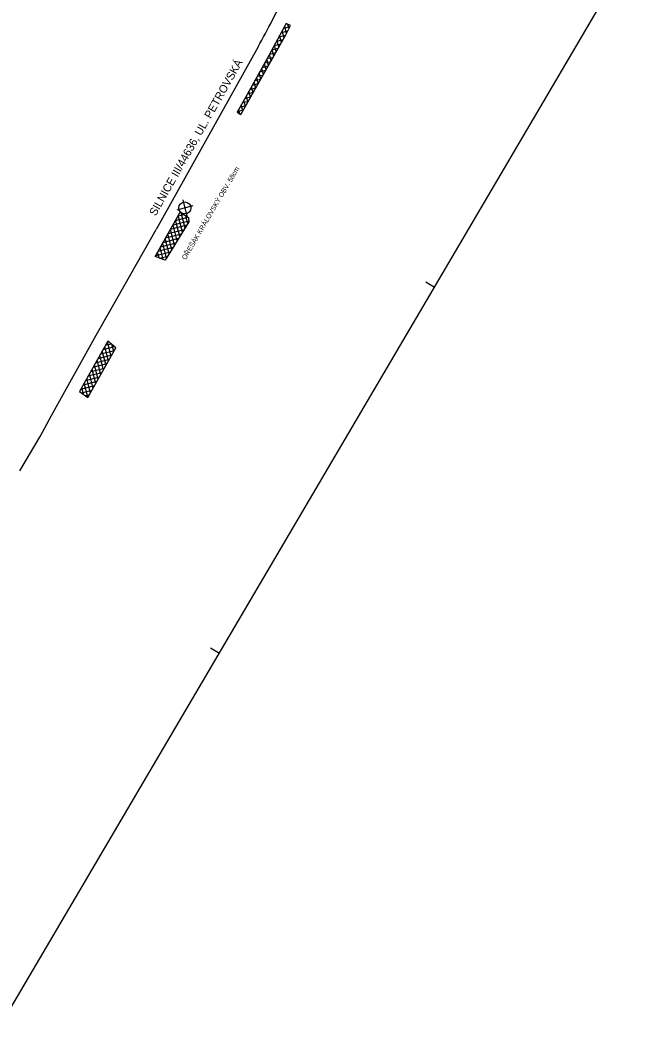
# Model space of a CAD drawing. Extents: x -559605 to -559051, y -1075984 to -1075185.
# Drawn here: x -559472.7 to -559320, y -1075984.5 to -1075737.3 of the extents above; entities that cross this region are included whole.
import ezdxf

# ---------------------------------------------------------------- set-up
doc = ezdxf.new("R2010")
doc.units = 0
for name, color, linetype in [('_kaceni_stromu', 7, 'Continuous'), ('_odstraneni_krovin', 7, 'Continuous'), ('_zarezani_asfaltu', 7, 'Continuous'), ('Legenda', 7, 'Continuous'), ('popis', 7, 'Continuous'), ('Ramecek_rozpiska', 7, 'Continuous')]:
    doc.layers.add(name, color=color, linetype=linetype)

msp = doc.modelspace()

# ---------------------------------------------------------------- linework, layer by layer
at = {"layer": '_kaceni_stromu'}
for p, q in [((-559429.87, -1075783.31), (-559433.87, -1075784.35)), ((-559432.39, -1075781.83), (-559431.35, -1075785.83))]:
    msp.add_line(p, q, dxfattribs=at)
msp.add_circle((-559431.87, -1075783.83), 1.49, dxfattribs=at)
at = {"layer": '_odstraneni_krovin'}
for p, q in [((-559407.41, -1075739.32), (-559405.83, -1075738.91)), ((-559406.7, -1075740.65), (-559407.17, -1075738.87)), ((-559406.83, -1075738.24), (-559406.83, -1075738.24)), ((-559406.09, -1075739.43), (-559406.35, -1075738.43)), ((-559409.15, -1075742.56), (-559407.53, -1075742.14)), ((-559408.57, -1075741.48), (-559406.91, -1075741.05)), ((-559407.97, -1075742.93), (-559408.42, -1075741.2)), ((-559407.99, -1075740.4), (-559406.37, -1075739.98)), ((-559407.33, -1075741.8), (-559407.79, -1075740.03)), ((-559410.31, -1075744.73), (-559408.76, -1075744.32)), ((-559409.88, -1075746.31), (-559410.3, -1075744.7)), ((-559409.73, -1075743.65), (-559408.14, -1075743.23)), ((-559409.24, -1075745.18), (-559409.67, -1075743.54)), ((-559408.61, -1075744.06), (-559409.05, -1075742.37)), ((-559411.16, -1075748.57), (-559411.55, -1075747.04)), ((-559411.47, -1075746.89), (-559409.99, -1075746.5)), ((-559410.52, -1075747.44), (-559410.93, -1075745.87)), ((-559410.89, -1075745.81), (-559409.37, -1075745.41)), ((-559412.43, -1075750.82), (-559412.82, -1075749.3)), ((-559412.69, -1075749.06), (-559411.22, -1075748.68)), ((-559411.79, -1075749.69), (-559412.19, -1075748.17)), ((-559412.08, -1075747.97), (-559410.61, -1075747.59)), ((-559414.52, -1075752.33), (-559413.07, -1075751.95)), ((-559413.7, -1075753.08), (-559414.09, -1075751.57)), ((-559413.91, -1075751.24), (-559412.45, -1075750.86)), ((-559413.07, -1075751.95), (-559413.46, -1075750.44)), ((-559413.3, -1075750.15), (-559411.84, -1075749.77)), ((-559415.74, -1075754.5), (-559414.3, -1075754.13)), ((-559414.98, -1075755.33), (-559415.37, -1075753.84)), ((-559415.13, -1075753.42), (-559413.68, -1075753.04)), ((-559414.34, -1075754.2), (-559414.73, -1075752.7)), ((-559416.96, -1075756.68), (-559415.53, -1075756.31)), ((-559416.25, -1075757.59), (-559416.64, -1075756.1)), ((-559416.35, -1075755.59), (-559414.91, -1075755.22)), ((-559415.62, -1075756.46), (-559416, -1075754.97)), ((-559418.28, -1075760.52), (-559418.56, -1075759.46)), ((-559418.21, -1075758.87), (-559416.76, -1075758.49)), ((-559417.53, -1075759.84), (-559417.92, -1075758.34)), ((-559417.59, -1075757.77), (-559416.15, -1075757.4)), ((-559416.89, -1075758.71), (-559417.28, -1075757.23)), ((-559418.84, -1075759.96), (-559417.38, -1075759.58)), ((-559418.02, -1075760.67), (-559417.99, -1075760.67)), ((-559434.17, -1075786.9), (-559431.1, -1075786.1)), ((-559433.56, -1075785.81), (-559432.12, -1075785.44)), ((-559432.45, -1075789.85), (-559433.52, -1075785.73)), ((-559431.79, -1075788.79), (-559432.77, -1075785.01)), ((-559431.14, -1075787.73), (-559431.65, -1075785.74)), ((-559436.01, -1075790.16), (-559432, -1075789.12)), ((-559434.41, -1075793.03), (-559435.42, -1075789.13)), ((-559435.39, -1075789.08), (-559431.31, -1075788.02)), ((-559433.76, -1075791.97), (-559434.79, -1075788)), ((-559434.78, -1075787.99), (-559430.89, -1075786.98)), ((-559433.1, -1075790.91), (-559434.15, -1075786.87)), ((-559437.23, -1075792.34), (-559433.36, -1075791.34)), ((-559435.72, -1075795.15), (-559436.7, -1075791.39)), ((-559436.62, -1075791.25), (-559432.68, -1075790.23)), ((-559435.06, -1075794.09), (-559436.06, -1075790.26)), ((-559438.45, -1075794.52), (-559434.73, -1075793.55)), ((-559437.21, -1075796.59), (-559437.97, -1075793.65)), ((-559437.84, -1075793.43), (-559434.05, -1075792.45)), ((-559436.37, -1075796.21), (-559437.33, -1075792.52)), ((-559439.07, -1075795.61), (-559435.41, -1075794.66)), ((-559438.24, -1075796.19), (-559438.6, -1075794.79)), ((-559438.05, -1075796.27), (-559436.1, -1075795.77)), ((-559452.08, -1075818.86), (-559449.25, -1075818.13)), ((-559450.74, -1075821.62), (-559451.65, -1075818.09)), ((-559451.47, -1075817.78), (-559450.1, -1075817.42)), ((-559450.1, -1075820.49), (-559451.02, -1075816.96)), ((-559449.46, -1075819.36), (-559449.93, -1075817.56)), ((-559453.92, -1075822.13), (-559450.53, -1075821.25)), ((-559453.3, -1075821.04), (-559449.92, -1075820.16)), ((-559452.01, -1075823.88), (-559452.92, -1075820.36)), ((-559452.69, -1075819.95), (-559449.3, -1075819.07)), ((-559451.37, -1075822.75), (-559452.29, -1075819.23)), ((-559455.14, -1075824.31), (-559451.75, -1075823.43)), ((-559453.92, -1075827.27), (-559454.83, -1075823.76)), ((-559454.53, -1075823.22), (-559451.14, -1075822.34)), ((-559453.28, -1075826.14), (-559454.19, -1075822.63)), ((-559452.64, -1075825.01), (-559453.56, -1075821.49)), ((-559456.36, -1075826.48), (-559452.98, -1075825.61)), ((-559455.19, -1075829.53), (-559456.1, -1075826.03)), ((-559455.75, -1075825.39), (-559452.37, -1075824.52)), ((-559454.55, -1075828.4), (-559455.46, -1075824.89)), ((-559457.58, -1075828.66), (-559454.21, -1075827.78)), ((-559456.95, -1075829.9), (-559457.37, -1075828.29)), ((-559456.97, -1075827.57), (-559453.59, -1075826.69)), ((-559455.83, -1075830.66), (-559456.74, -1075827.16)), ((-559457.44, -1075829.55), (-559454.82, -1075828.87)), ((-559456.49, -1075830.24), (-559455.43, -1075829.96))]:
    msp.add_line(p, q, dxfattribs=at)
for points in [[(-559418.94, -1075760.13), (-559418, -1075760.68), (-559406.86, -1075740.97), (-559405.71, -1075738.67), (-559406.83, -1075738.24), (-559411.57, -1075747.06), (-559416.85, -1075756.48)], [(-559439.17, -1075795.8), (-559433.02, -1075784.85), (-559430.99, -1075786.17), (-559430.85, -1075787.27), (-559436.72, -1075796.77), (-559437.85, -1075796.36)], [(-559450.89, -1075816.74), (-559457.89, -1075829.22), (-559455.85, -1075830.7), (-559448.93, -1075818.4)]]:
    msp.add_lwpolyline(points, close=True, dxfattribs=at)
at = {"layer": '_zarezani_asfaltu'}
for p, q in [((-559410.18, -1075737.33), (-559379.47, -1075677.22)), ((-559413.74, -1075743.99), (-559438.95, -1075789.14))]:
    msp.add_line(p, q, dxfattribs=at)
msp.add_lwpolyline([(-559472.65, -1075848.87), (-559467.68, -1075840.37), (-559464.83, -1075835.19), (-559453.82, -1075815.27), (-559450.09, -1075808.74), (-559438.95, -1075789.14)], dxfattribs=at)
msp.add_arc((-559592.65, -1075644.11), 204.9, 330.8259, 332.9381, dxfattribs=at)
at = {"layer": 'Ramecek_rozpiska'}
for p, q in [((-559476.53, -1075984.46), (-559050.89, -1075260.28)), ((-559372.27, -1075802.14), (-559370.12, -1075803.41)), ((-559425.48, -1075892.67), (-559423.32, -1075893.93))]:
    msp.add_line(p, q, dxfattribs=at)

# ---------------------------------------------------------------- texts
at = {"layer": 'Legenda'}
msp.add_text('OŘEŠÁK KRÁLOVSKÝ OBV. 58cm', height=1.2, rotation=59.5553, dxfattribs=at).set_placement((-559431.66, -1075796.77))
at = {"layer": 'popis'}
msp.add_text('SILNICE III/44636, UL. PETROVSKÁ', height=1.98, rotation=60.503, dxfattribs=at).set_placement((-559439.08, -1075785.96))

doc.saveas('drawing.dxf')
